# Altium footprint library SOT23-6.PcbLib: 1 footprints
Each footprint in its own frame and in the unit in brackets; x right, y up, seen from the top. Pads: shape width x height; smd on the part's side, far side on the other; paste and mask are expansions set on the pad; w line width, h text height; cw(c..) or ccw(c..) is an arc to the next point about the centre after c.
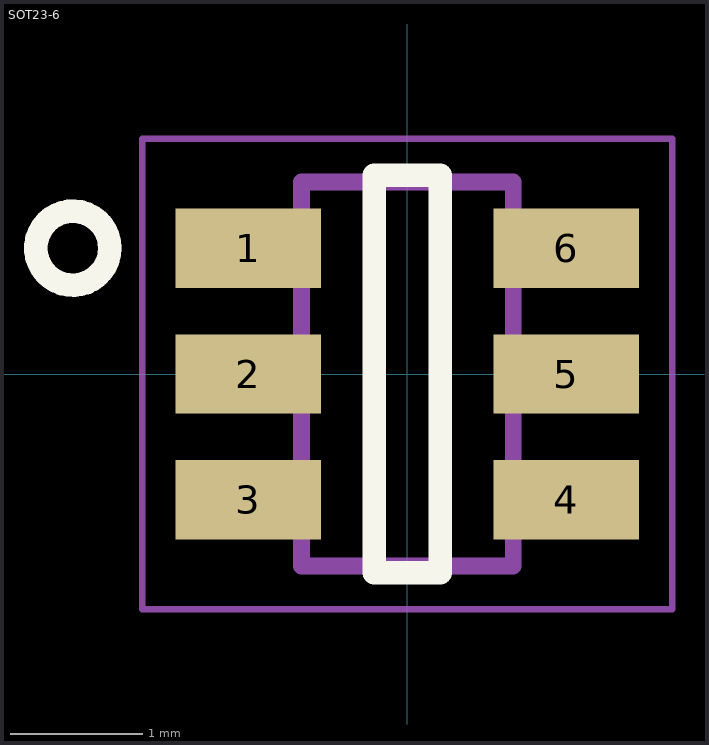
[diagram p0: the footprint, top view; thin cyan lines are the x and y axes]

## SOT23-6 [mm] "IC DAC R-R LP 12BIT SOT23-6"
height 1.45
pads (6):
  rect 1.1x0.6 smd: 1(-1.2,0.95) 2(-1.2,0) 3(-1.2,-0.95) 4(1.2,-0.95) 5(1.2,0) 6(1.2,0.95)
Top Overlay:
  circle w0.178: c-2.525,0.95 r0.279
  lines w0.178: -0.25,-1.5 -0.25,1.5 0.25,1.5 0.25,-1.5 -0.25,-1.5
  text ".Designator" at -1.524,3 h1.02
Mechanical 5:
  circle w0.127: c-2.5,0.95 r0.279
  lines w0.127: -0.8,-1.45 -0.8,1.45 0.8,1.45 0.8,-1.45 -0.8,-1.45
Mechanical 9:
  text ".Designator" at -1.524,-0.508 h1.02
Mechanical 15:
  lines w0.05: -2,-1.775 -2,1.775 2,1.775 2,-1.775 -2,-1.775
3D body: height 1.45, standoff 0, extent -0.8,-1.45 0.8,1.45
